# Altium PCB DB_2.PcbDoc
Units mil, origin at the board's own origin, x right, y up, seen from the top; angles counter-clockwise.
Board outline 1675 x 1950 mil, 4 copper layers (Top Layer, Signal Layer 1, Ground, Bottom Layer), stack 30.634 mil thick; 76 components, 70 nets, 293 pads, 58 vias.
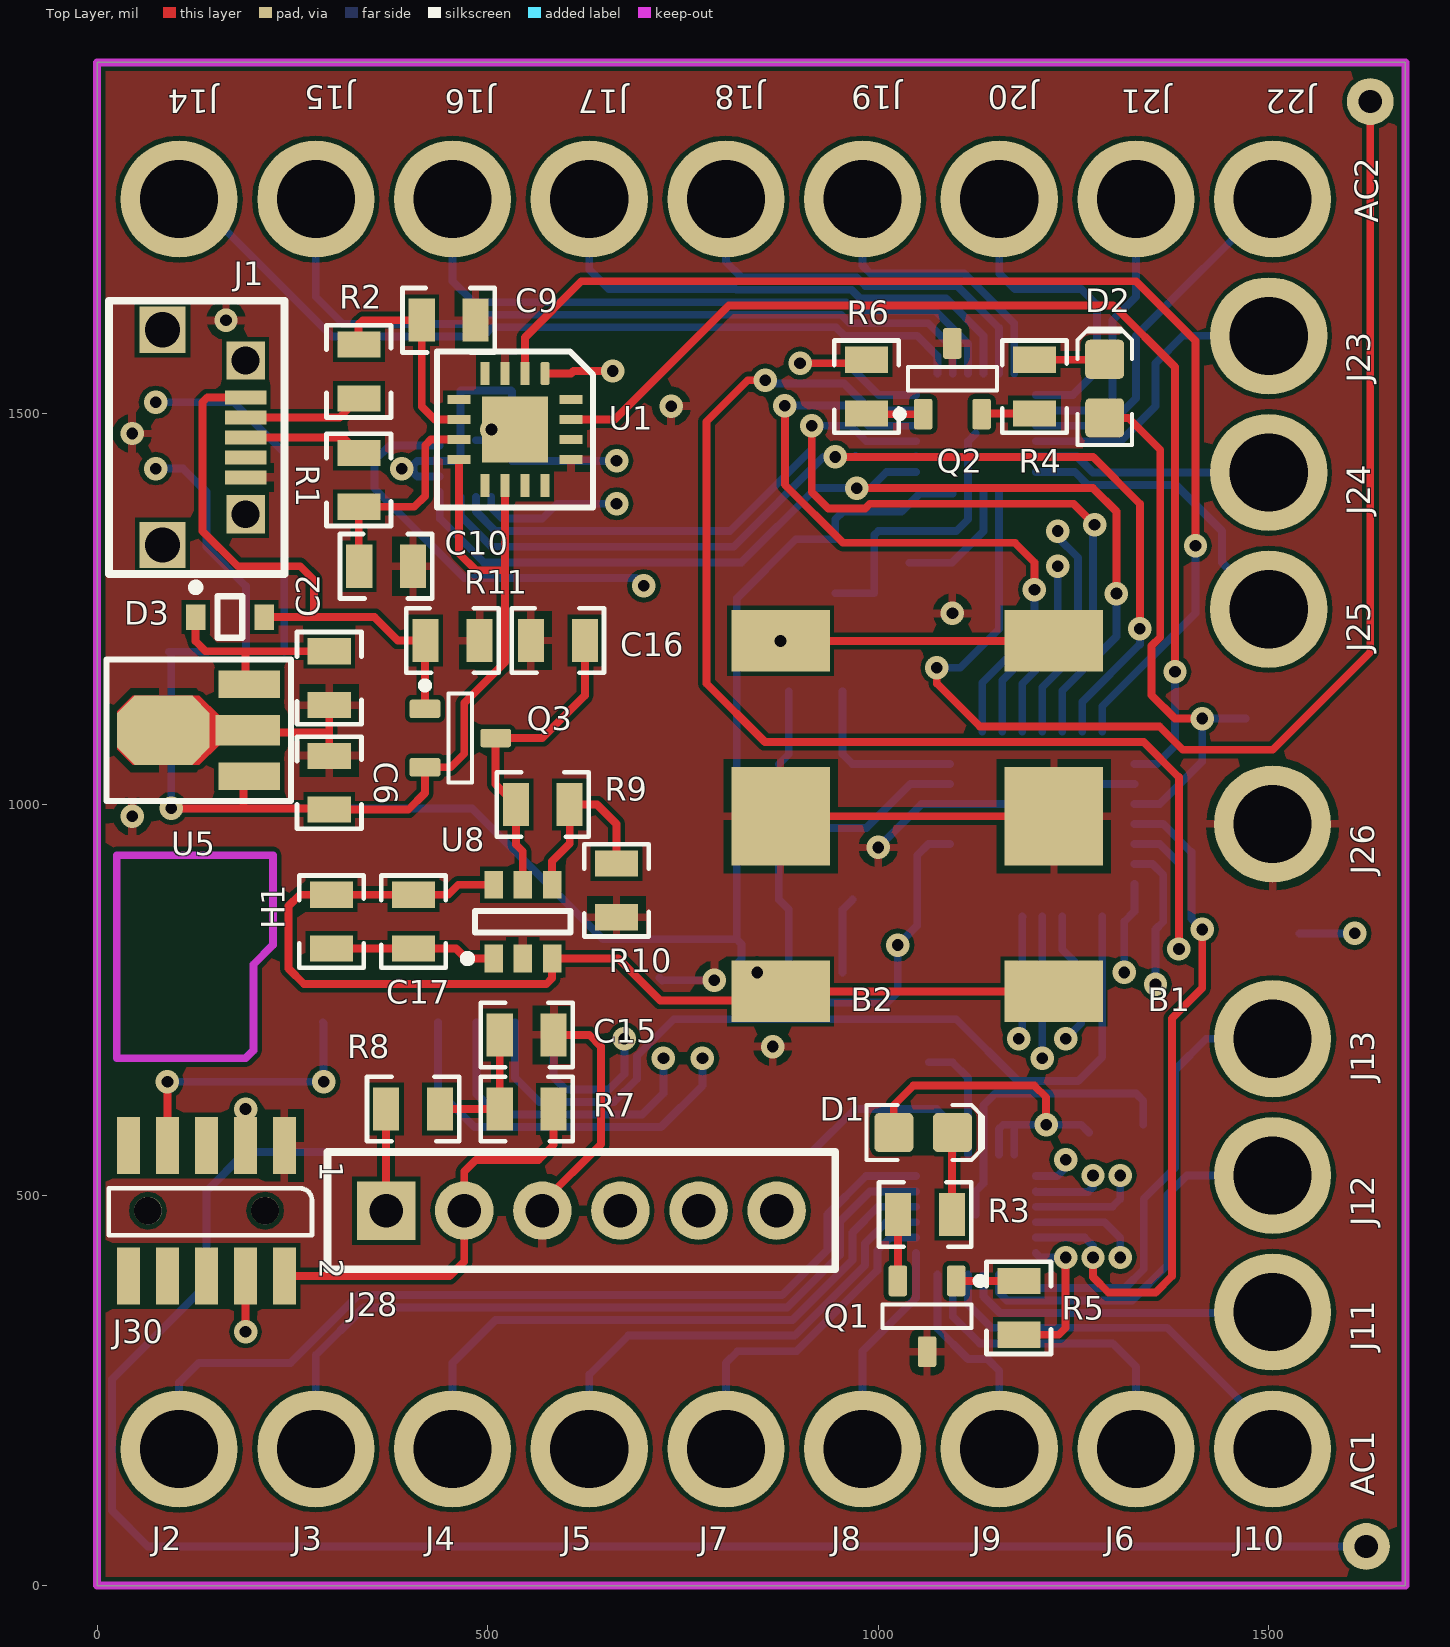
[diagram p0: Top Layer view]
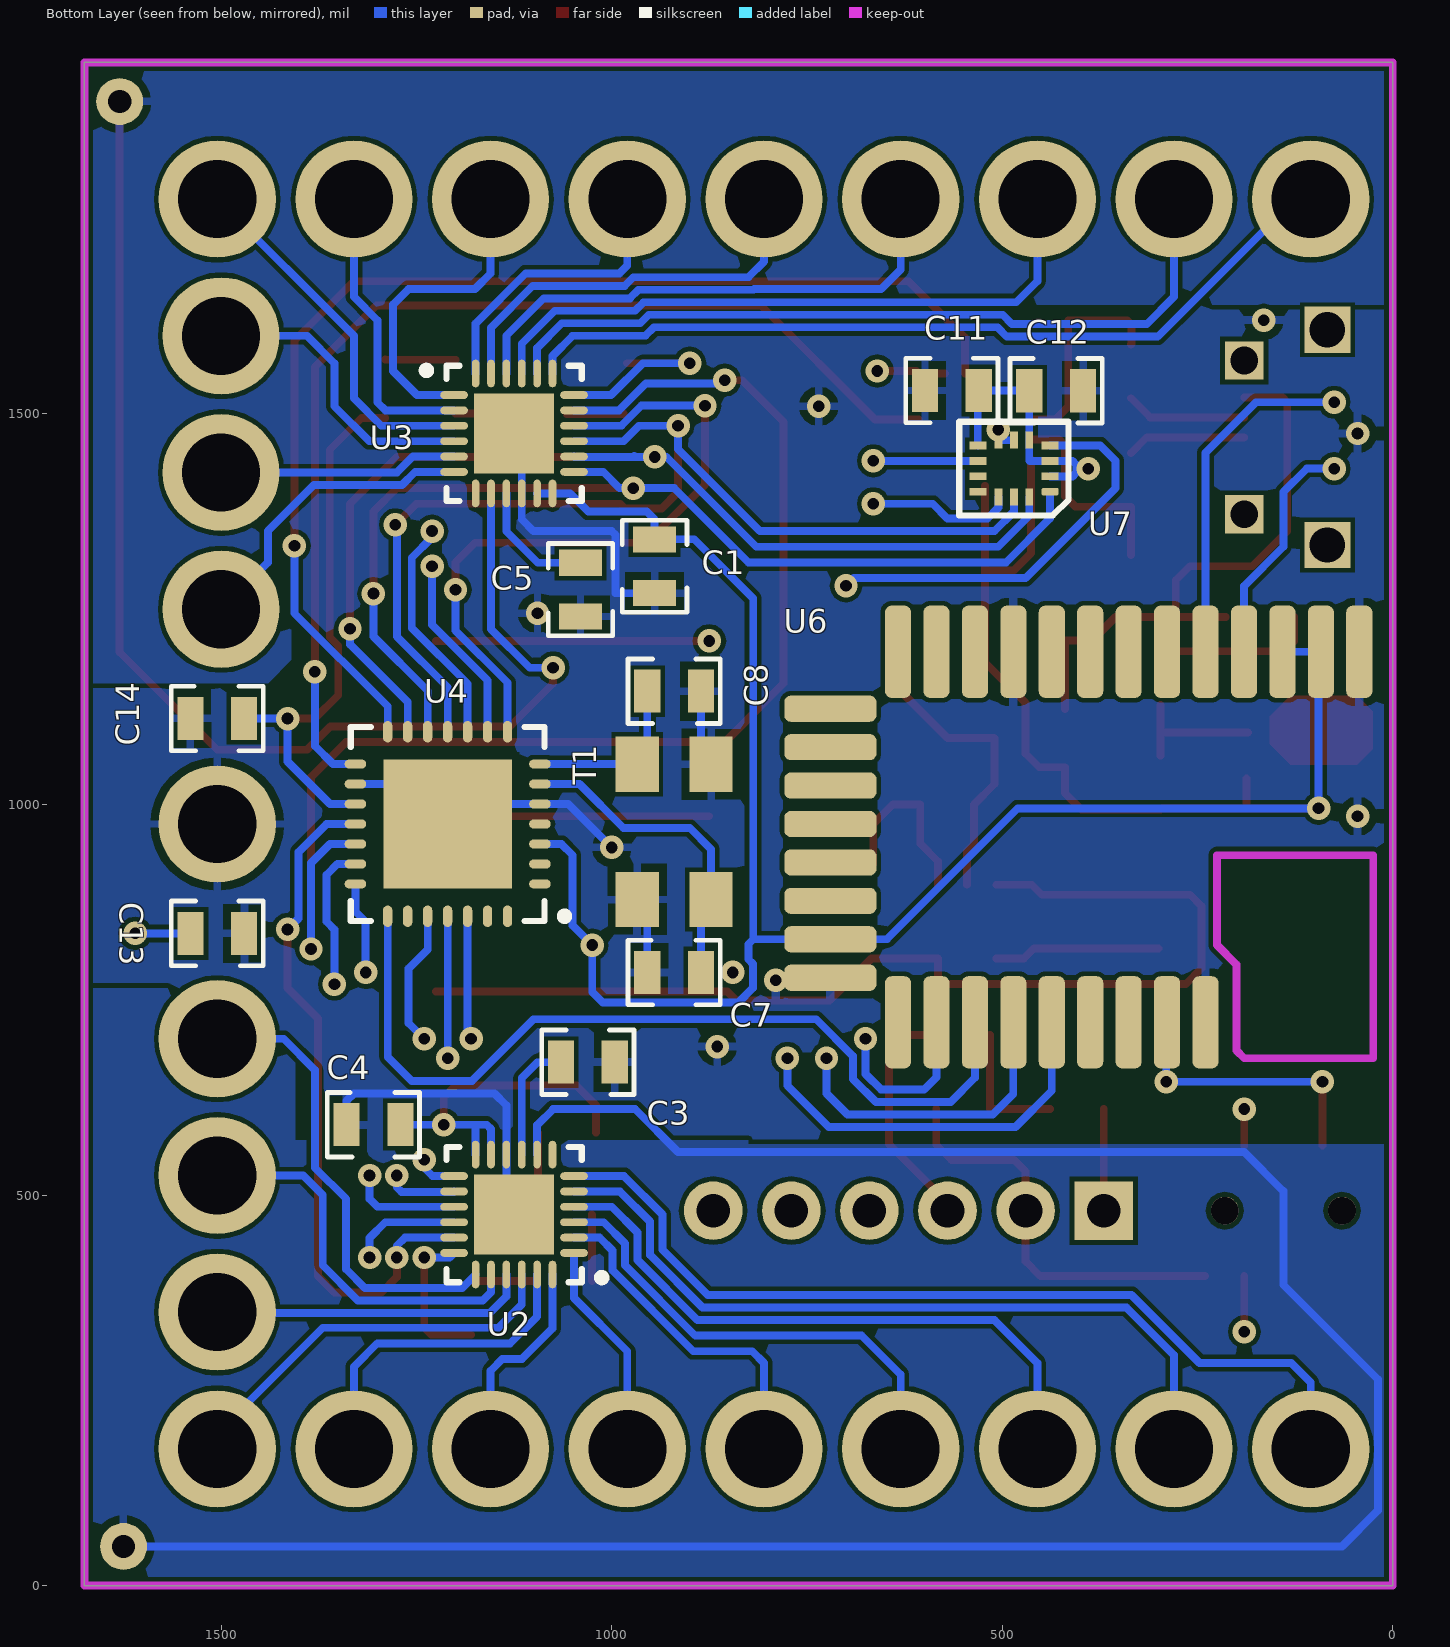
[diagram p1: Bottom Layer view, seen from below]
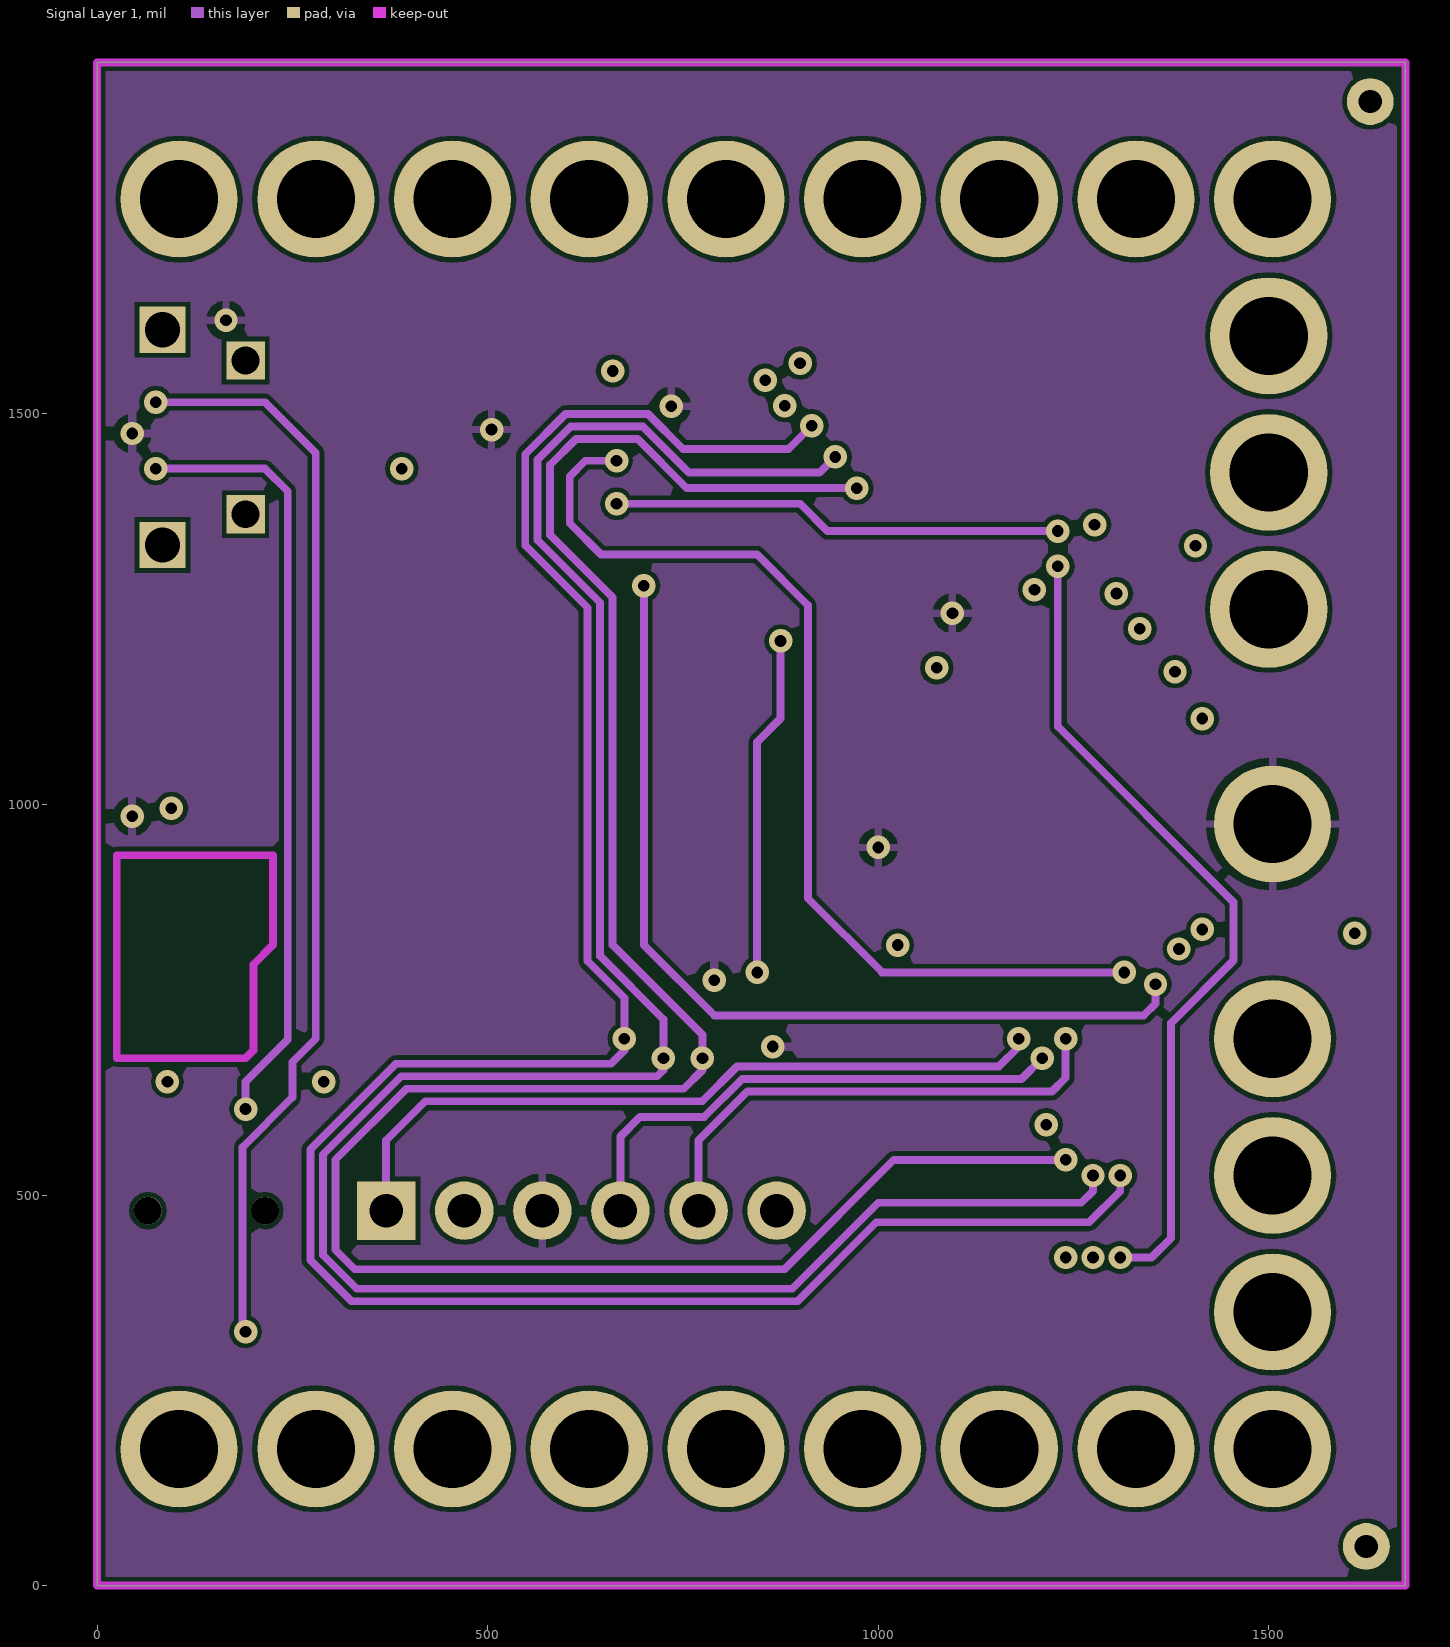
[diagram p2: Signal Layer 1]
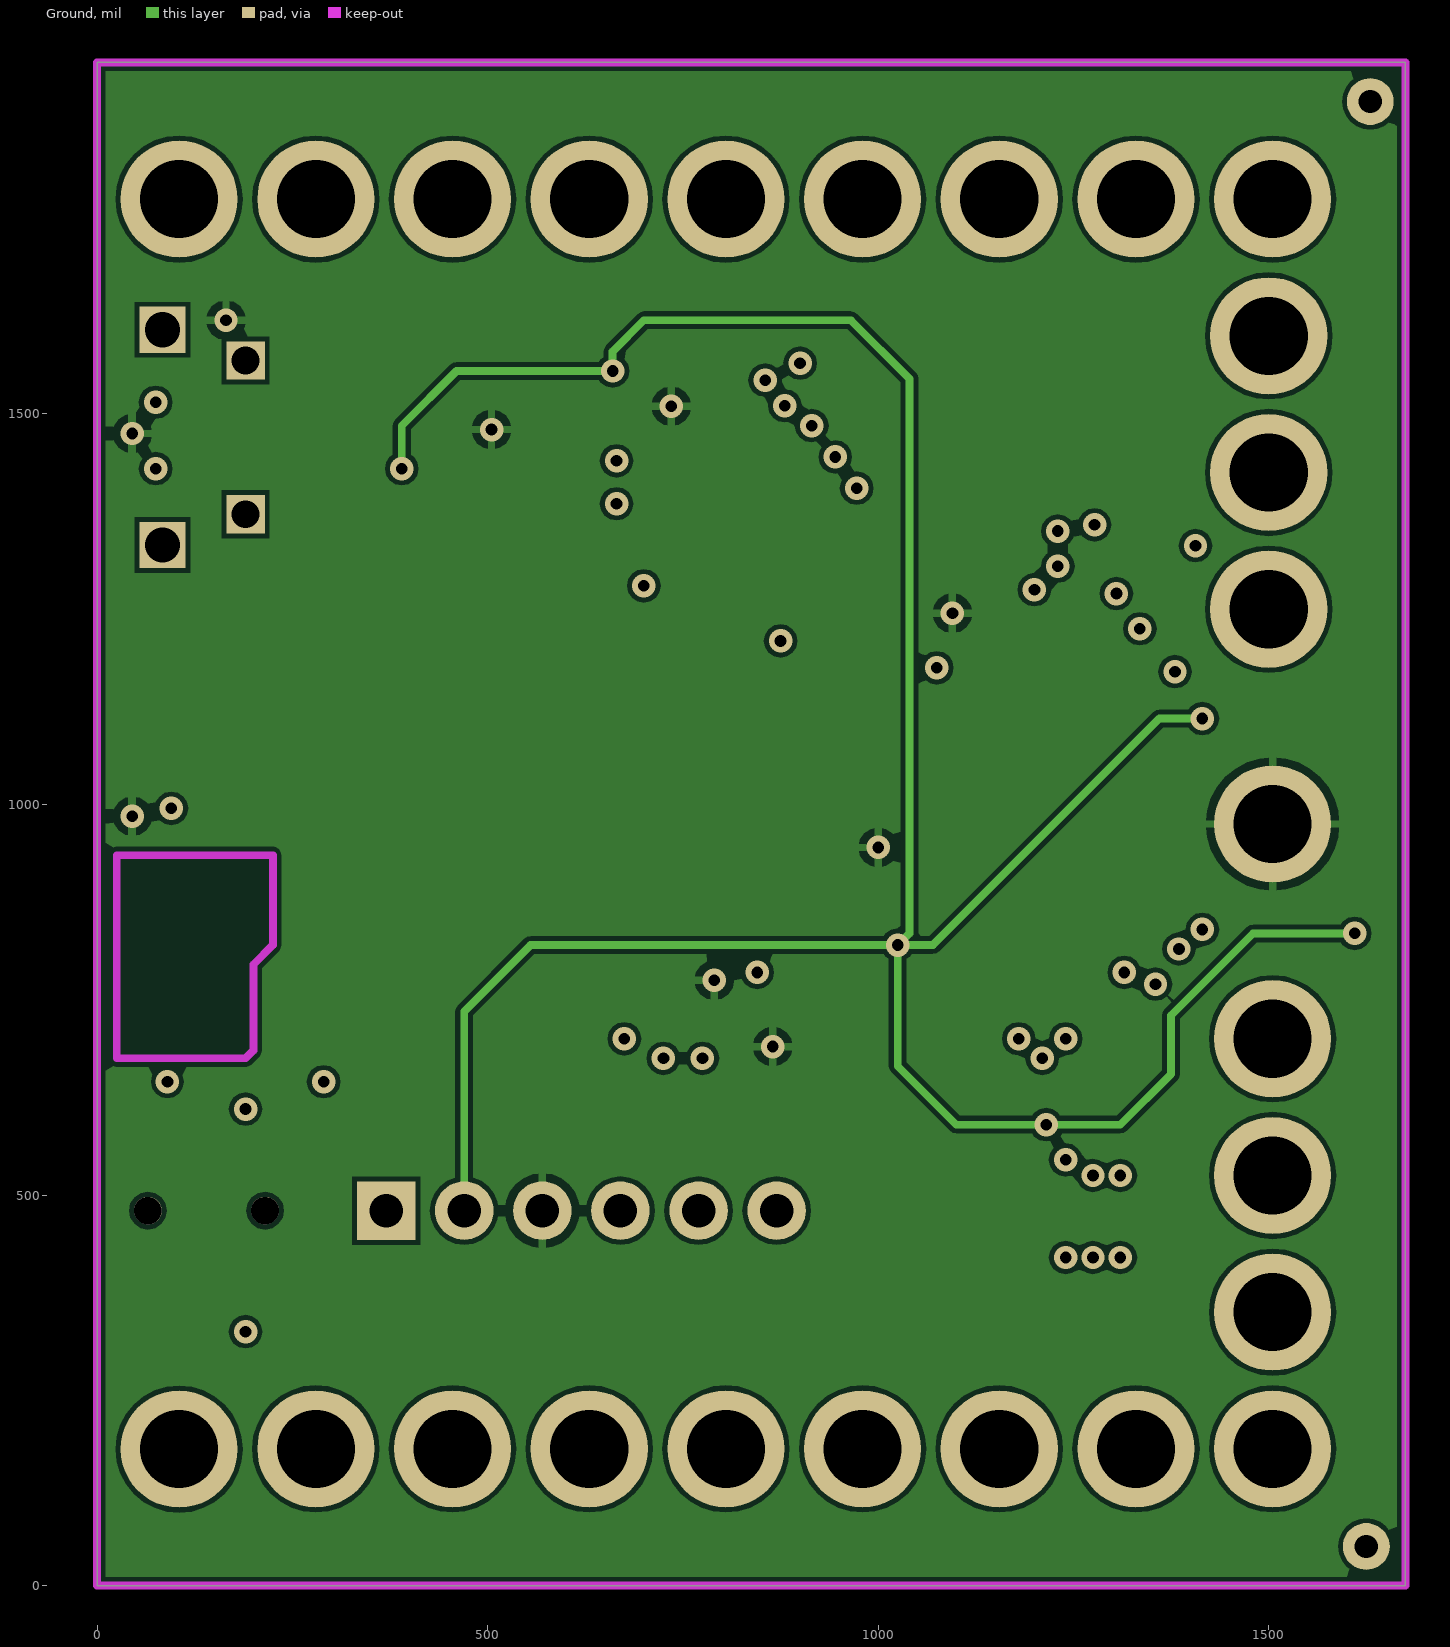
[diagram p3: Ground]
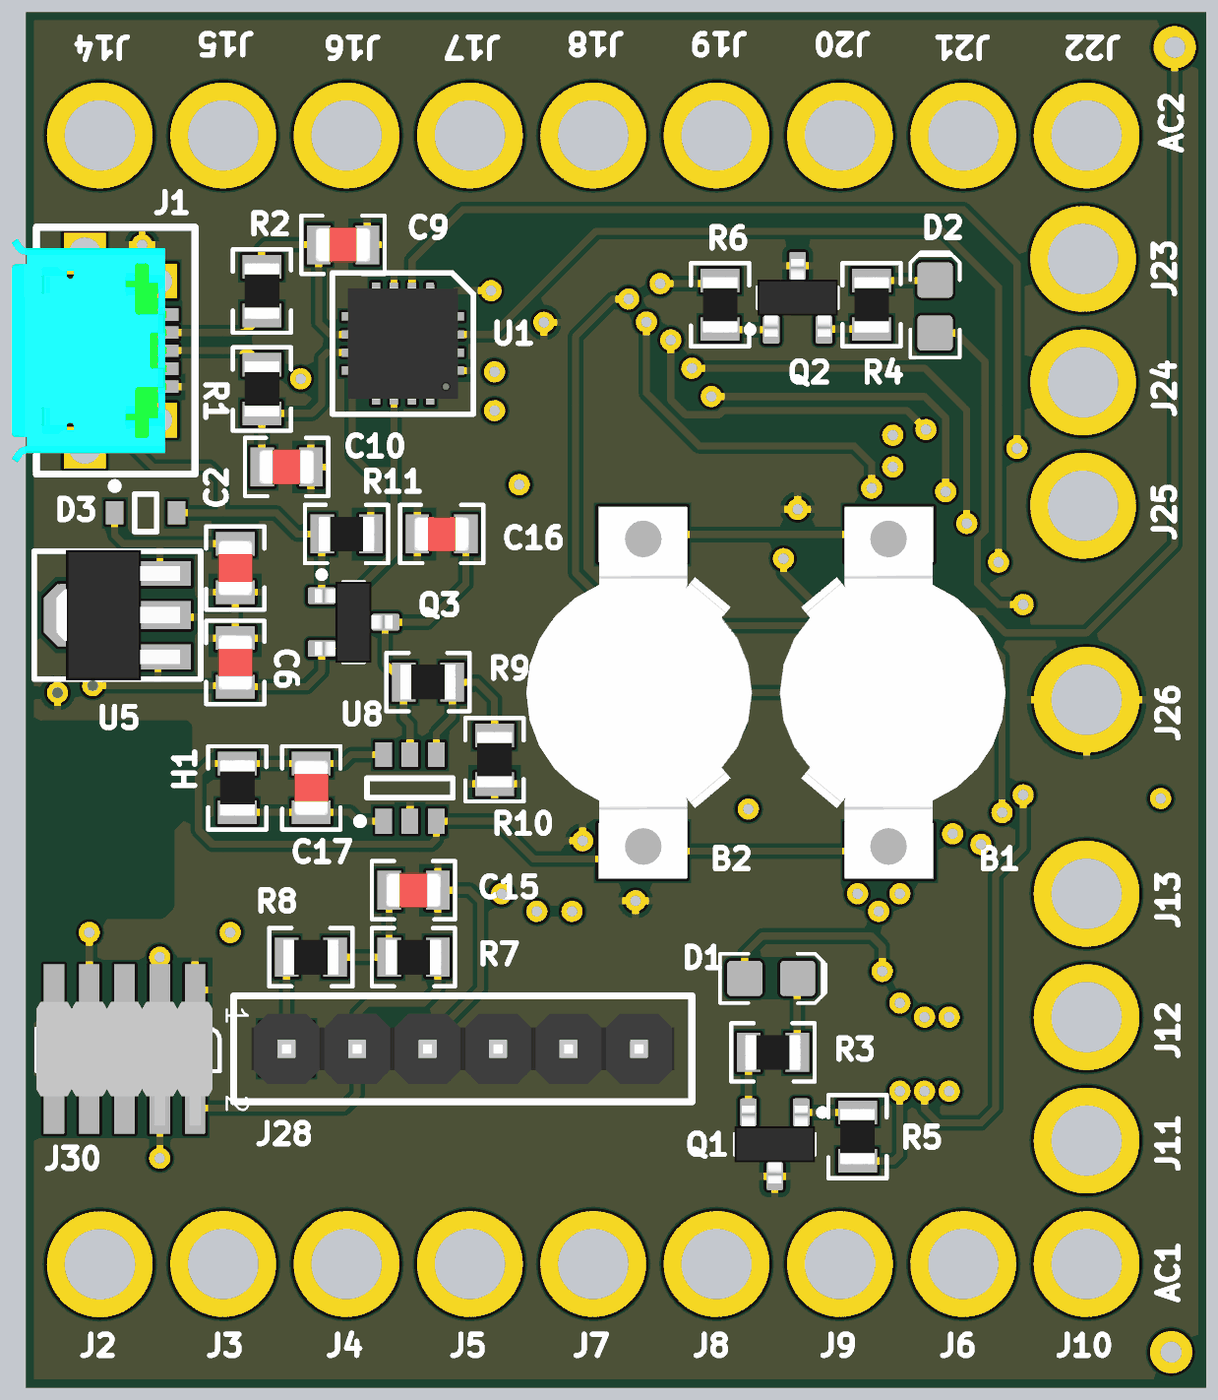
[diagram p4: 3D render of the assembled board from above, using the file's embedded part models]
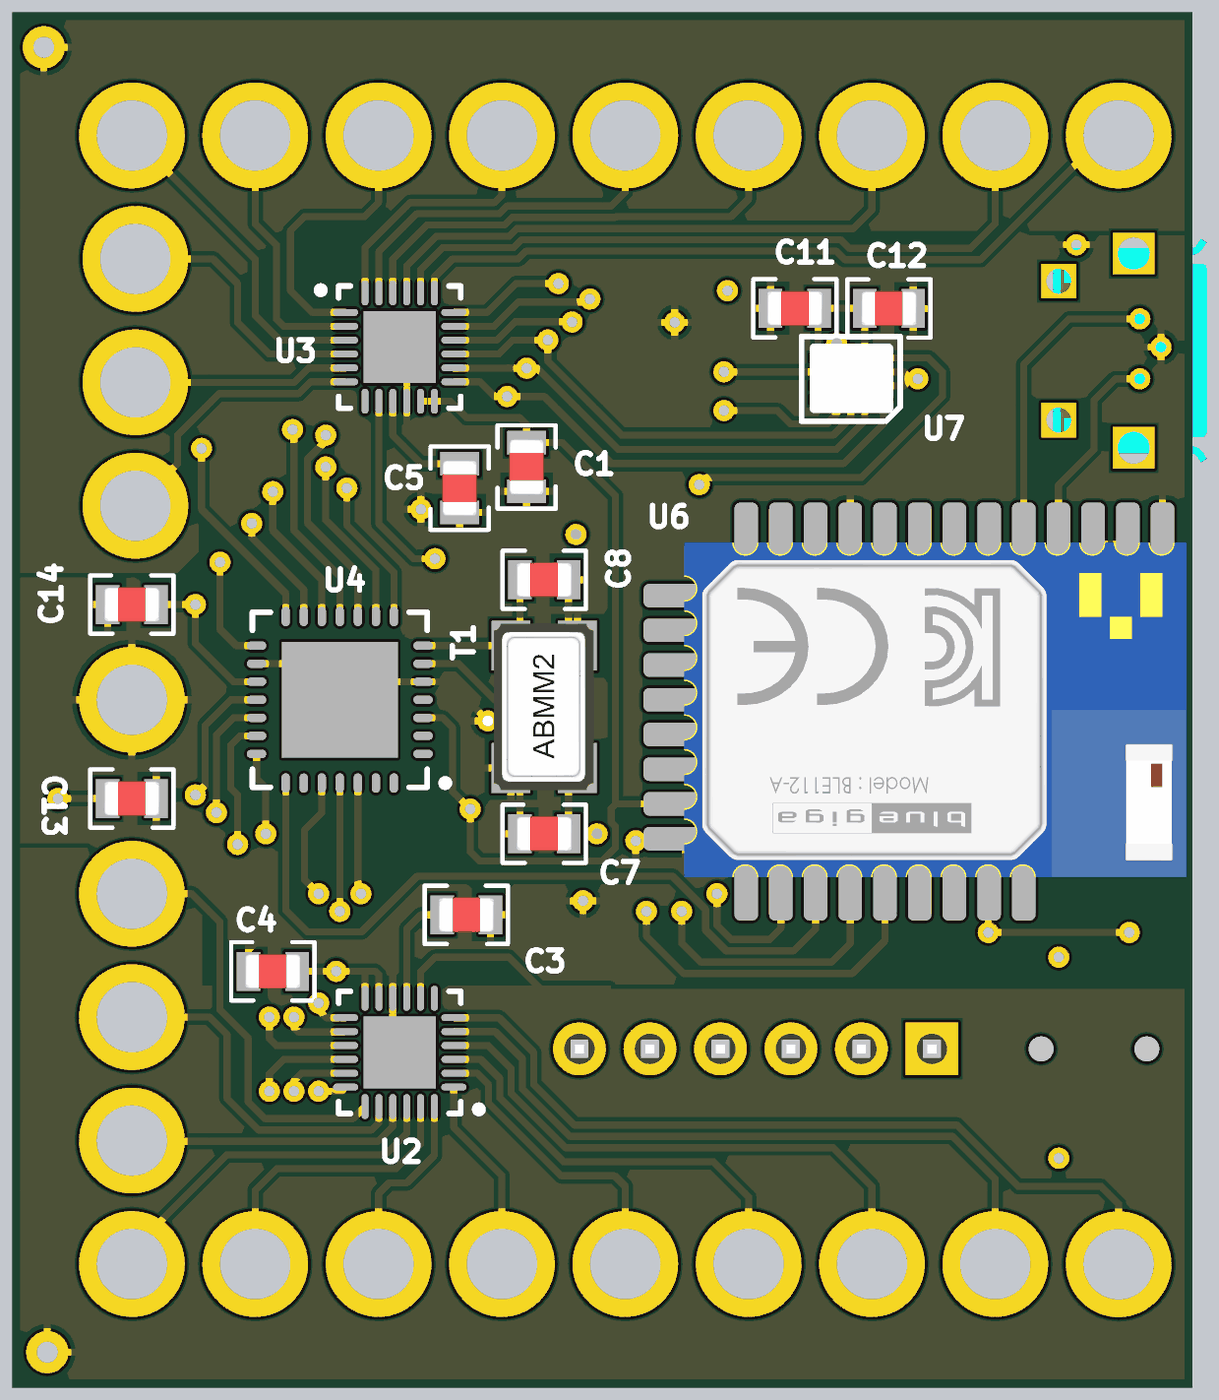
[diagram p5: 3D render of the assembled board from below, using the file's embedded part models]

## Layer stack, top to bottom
Top Solder: solder mask 0.4, Solder Resist, Dk 3.5
Top Layer: signal copper 1.4
Dielectric 1: core 10, FR-4, Dk 4.2
Signal Layer 1: signal copper 1.417
Dielectric 3: prepreg 5, Dk 4.2
Ground: signal copper 1.417
Dielectric 2: core 10, Dk 4.2
Bottom Layer: signal copper 1.4
Bottom Solder: solder mask 0.4, Solder Resist, Dk 3.5

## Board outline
0,0 1675,0 1675,1950 0,1950

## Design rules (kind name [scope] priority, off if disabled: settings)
Clearance [All] p1: gap=6 ignorepadtopadclearanceinfootprint=FALSE except(0: Arc-Hole Track-Hole SMDPad-Hole THPad-Hole Via-Hole Fill-Hole Poly-Hole Region-Hole Text-Hole)
HoleSize [All] p1: absolutevalues=TRUE maxlimit=200 minlimit=1 maxpercent=80.000 minpercent=20.000
HoleToHoleClearance [All] p1: gap=6 allowstackedmicrovias=TRUE
MinimumSolderMaskSliver [All] p1: minsoldermaskwidth=6
PolygonConnect [All] p1: connectstyle=Relief reliefconductorwidth=10 reliefentries=4 polygonreliefangle="90 Angle" airgapwidth=10
RoutingVias [All] p1: holewidth=28 width=50 viastyle="Through Hole" minholewidth=3 minwidth=8 maxholewidth=28 maxwidth=50
SilkToSilkClearance [All] p1: silktosilkclearance=6
SilkToSolderMaskClearance [IsPad] p1: minsilkscreentomaskgap=6 clearancetoexposedcopper=TRUE
SolderMaskExpansion [All] p1: expansion=4
Width [All] p1: maxlimit=50 minlimit=6 preferedwidth=10
25 further rules are at their usual default settings.

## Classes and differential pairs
component class Battery: B1 B2 C2 C6 C9 C10 C16 C17 D3 H1 J1 Q3 R1 R2 R9 R10 R11 U5 U8
component class Sheet-2: AC1 AC2 C1 C3 C4 C5 C7 C8 C11 C12 C13 C14 C15 D1 D2 J2 J3 J4 J5 J6 J7 J8 J9 J10 J11 J12 J13 J14 J15 J16 J17 J18 J19 J20 J21 J22 J23 J24 J25 J26 J28 J30 Q1 Q2 R3 R4 R5 R6 R7 R8 T1 U1 U2 U3 U4 U6 U7

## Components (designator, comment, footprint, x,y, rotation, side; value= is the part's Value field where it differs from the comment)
AC1 "AC_Shield" AC_SHIELD 1625,50 r0 top
AC2 "AC_Shield" AC_SHIELD 1630,1900 r90 top
B1 "XR48" XR48 1225,985 r270 top
B2 "XR48" XR48 875,985 r90 top
C1 "0.1µF" CAP-0805(2012)-R 945,1305 r270 bottom
C2 "0.33µF" CAP-0805(2012)-R 297.17,1161.73 r270 top
C3 "10000pF" CAP-0805(2012)-R 1030.55,670 r180 bottom
C4 "0.1µF" CAP-0805(2012)-R 1305,590 r0 bottom
C5 "10000pF" CAP-0805(2012)-R 1040,1275 r270 bottom
C6 "0.1µF" CAP-0805(2012)-R 297.17,1027.83 r90 top
C7 "18pF" CAP-0805(2012)-R 920,785 r0 bottom
C8 "18pF" CAP-0805(2012)-R 920,1145 r180 bottom
C9 "47pF" CAP-0805(2012)-R 450,1620 r180 top
C10 "47pF" CAP-0805(2012)-R 370,1305 r180 top
C11 "0.1µF" CAP-0805(2012)-R 564.45,1530 r180 bottom
C12 "10000pF" CAP-0805(2012)-R 430.87,1529.68 r0 bottom
C13 "0.1µF" CAP-0805(2012)-R 1505,835 r180 bottom
C14 "0.1µF" CAP-0805(2012)-R 1505,1110 r0 bottom
C15 "0.1uF" CAP-0805(2012)-R 550,705 r0 top
C16 "10uF" CAP-0805(2012)-R 590,1210 r180 top
C17 "4.7uF" CAP-0805(2012)-R 405,850 r270 top
D1 "YELLOW" LED-0805-A 1057.5,580 r0 top
D2 "YELLOW" LED-0805-A 1290,1532.5 r90 top
D3 "Shottky_Diode" SOD-323-2 170,1240 r0 top
H1 "H-0805(2012)" H-0805(2012)-H 300,850 r90 top
J1 "USB" USB_CONNECTOR_5P_MICRO_USB_FCI 190,1470 r270 top
J2 "Conductive Thread" THREAD_HOLE 105,174.61 r180 top
J3 "Conductive Thread" THREAD_HOLE 280,175 r180 top
J4 "Conductive Thread" THREAD_HOLE 455,175 r180 top
J5 "Conductive Thread" THREAD_HOLE 630,175 r180 top
J6 "Conductive Thread" THREAD_HOLE 1330,175 r180 top
J7 "Conductive Thread" THREAD_HOLE 805,175 r180 top
J8 "Conductive Thread" THREAD_HOLE 980,175 r180 top
J9 "Conductive Thread" THREAD_HOLE 1155,175 r180 top
J10 "Conductive Thread" THREAD_HOLE 1505,175 r180 top
J11 "Conductive Thread" THREAD_HOLE 1505,350 r180 top
J12 "Conductive Thread" THREAD_HOLE 1505,525 r180 top
J13 "Conductive Thread" THREAD_HOLE 1505,700 r270 top
J14 "Conductive Thread" THREAD_HOLE 105,1775 r0 top
J15 "Conductive Thread" THREAD_HOLE 280,1775 r180 top
J16 "Conductive Thread" THREAD_HOLE 455,1775 r0 top
J17 "Conductive Thread" THREAD_HOLE 630,1775 r180 top
J18 "Conductive Thread" THREAD_HOLE 805,1775 r180 top
J19 "Conductive Thread" THREAD_HOLE 980,1775 r180 top
J20 "Conductive Thread" THREAD_HOLE 1155,1775 r180 top
J21 "Conductive Thread" THREAD_HOLE 1330,1775 r180 top
J22 "Conductive Thread" THREAD_HOLE 1505,1775 r180 top
J23 "Conductive Thread" THREAD_HOLE 1500,1600 r90 top
J24 "Conductive Thread" THREAD_HOLE 1500,1425 r90 top
J25 "Conductive Thread" THREAD_HOLE 1500,1250 r90 top
J26 "Conductive Thread" THREAD_HOLE 1505,975 r180 top
J28 "Header 6 pin" HEADER-6-100MIL 370,480 r0 top
J30 "GRPB052VWQP-RC" GRPB052VWQP-RC 40,563.5 r270 top
Q1 "Value" SOT23-3 1062.6,344.72 r90 top
Q2 "Value" SOT23-3 1095,1545 r270 top
Q3 "DMP1045U" SOT23-3 465,1085 r180 top
R1 "27" R-0805(2012)-R 335,1415.55 r270 top
R2 "27" R-0805(2012)-R 335,1554.45 r90 top
R3 "30" R-0805(2012)-R 1060,475 r0 top
R4 "30" R-0805(2012)-R 1200,1535 r90 top
R5 "1k" R-0805(2012)-R 1180,355.55 r270 top
R6 "1k" R-0805(2012)-R 985,1535 r270 top
R7 "10k" R-0805(2012)-R 550,610 r0 top
R8 "330" R-0805(2012)-R 404.45,610 r0 top
R9 "976KR" R-0805(2012)-R 570.55,1000 r0 top
R10 "562KR" R-0805(2012)-R 665,890 r270 top
R11 "10KR" R-0805(2012)-R 455,1210 r180 top
T1 "8MHz" CRYSTAL-8MHZ 920,965 r90 bottom
U1 "FT230XQ-R" QFN-16 535,1480 r270 top
U2 "ADI-AD7147" LFCSP_WQ 1125,475 r0 bottom
U3 "ADI-AD7147" LFCSP_WQ 1125,1475 r180 bottom
U4 "PIC18F25K80" MCHP-QFN-S-MM28_N 1210,975 r0 bottom
U5 "L78L33ACUTR" SOT89-3 130,1095 r180 top
U6 "BLE112-A-V1" BLE112-A-V1 720,1195.47 r270 bottom
U7 "LSM6DS3H" LGA-14 485,1430 r0 bottom
U8 "MCP1640BT-I/CHY" MCHP-SOT-23-CHY6_L 545,850 r90 top

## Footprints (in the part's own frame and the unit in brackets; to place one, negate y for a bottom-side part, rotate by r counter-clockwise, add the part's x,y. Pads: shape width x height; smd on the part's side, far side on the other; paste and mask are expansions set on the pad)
AC_SHIELD [mil]
  round 60 hole 30: 1(0,0)
BLE112-A-V1 [mm] "CLASS 2 BLTOOTH 4.0 MODULE"
  rrect50% 3x0.85 smd: 1(0,17.2) 2(0,15.95) 3(0,14.7) 4(0,13.45) 5(0,12.2) 6(0,10.95) 7(0,9.7) 8(0,8.45) 9(0,7.2) 10(0,5.95) 11(0,4.7) 12(0,3.45) 13(0,2.2) 22(12.05,2.2) 23(12.05,3.45) 24(12.05,4.7) 25(12.05,5.95) 26(12.05,7.2) 27(12.05,8.45) 28(12.05,9.7) 29(12.05,10.95) 30(12.05,12.2)
  rrect50% 0.85x3 smd: 14(1.85,0) 15(3.1,0) 16(4.35,0) 17(5.6,0) 18(6.85,0) 19(8.1,0) 20(9.35,0) 21(10.6,0)
  body extent -0.06,-0.03 11.99,18.07, height 2.3
CAP-0805(2012)-R [mm] "Capacitor 0805(2012) Reflow"
  rect 0.85x1.4 smd: 1(-0.875,0) 2(0.875,0)
  silkscreen extent -1.5,-1.05 1.5,1.05, body extent -1,-0.63 1,0.63, height 0.78
CRYSTAL-8MHZ [mm] "ABRACON ABMM2-8.000MHZ-E2-T"
  rect 1.8x1.4 smd: 1(-2.2,-1.2) 2(-2.2,1.2) 2(2.2,-1.2) 3(2.2,1.2)
  body extent -3,-1.78 3,1.82, height 1.21
GRPB052VWQP-RC [mm] "CONN HEADER .050\" 10PS DL SMD AU"
  rect 1.85x0.74 smd: 1(0,5.08) 2(4.25,5.08) 3(0,3.81) 4(4.25,3.81) 5(0,2.54) 6(4.25,2.54) 7(0,1.27) 8(4.25,1.27) 9(0,0) 10(4.25,0)
  round 0.9 hole 0.9 unplated: 21(2.121,0.635) 22(2.121,4.445)
  silkscreen extent 1.4,-0.63 2.92,5.97, body extent -0.62,-0.63 4.88,5.72, height 4.1
H-0805(2012)-H [mm] "Inductor 0805(2012) Reflow"
  rect 0.85x1.4 smd: 1(-0.875,0) 2(0.875,0)
  silkscreen extent -1.5,-1.05 1.5,1.05, body extent -1,-0.62 1,0.63, height 0.5
HEADER-6-100MIL [mil] "100 mil spacing"
  rect 75x75 hole 43: 1(0,0)
  round 75 hole 43: 2(100,0) 3(200,0) 4(300,0) 5(400,0) 6(500,0)
  silkscreen extent -75,-75 575,75, body extent -50,-50 550,50, height 339
LED-0805-A [mil]
  round 20 on Mech14: 0(0,0)
  rrect25% 50x50 smd: A(-37.5,0) K(37.5,0)
  Top Layer pour cut-out: -15,30 15,30 15,-30 -15,-30
  silkscreen extent -72,-35 77,35, body extent -39,-25 39,25, height 31
LFCSP_WQ [mm] "QFN, 24-Leads, Body 4x4mm, Pitch 0.5mm, Thermal Pad 2.5x2.5mm, IPC Medium Density"
  oval 0.9x0.25 smd: 1(-1.95,1.25) 2(-1.95,0.75) 3(-1.95,0.25) 4(-1.95,-0.25) 5(-1.95,-0.75) 6(-1.95,-1.25) 13(1.95,-1.25) 14(1.95,-0.75) 15(1.95,-0.25) 16(1.95,0.25) 17(1.95,0.75) 18(1.95,1.25)
  oval 0.25x0.9 smd: 7(-1.25,-1.95) 8(-0.75,-1.95) 9(-0.25,-1.95) 10(0.25,-1.95) 11(0.75,-1.95) 12(1.25,-1.95) 19(1.25,1.95) 20(0.75,1.95) 21(0.25,1.95) 22(-0.25,1.95) 23(-0.75,1.95) 24(-1.25,1.95)
  rect 2.6x2.6 smd: 25(0,0)
  silkscreen extent -2.97,-2.2 2.2,2.2, body extent -2.05,-2.05 2.05,2.05, height 1
LGA-14 [mm] "LGA-14 2.5X3X0.86 14L"
  rrect50% 0.55x0.25 smd: 1(-1.175,0.75)
  rect 0.55x0.25 smd: 2(-1.175,0.25) 3(-1.175,-0.25) 4(-1.175,-0.75) 8(1.175,-0.75) 9(1.175,-0.25) 10(1.175,0.25) 11(1.175,0.75)
  rect 0.25x0.55 smd: 5(-0.5,-0.925) 6(0,-0.925) 7(0.5,-0.925) 12(0.5,0.925) 13(0,0.925) 14(-0.5,0.925)
  silkscreen extent -1.78,-1.52 1.78,1.52, body extent -1.52,-1.27 1.48,1.23, height 0.86
MCHP-QFN-S-MM28_N [mm] "QFN, 28-Leads, Body 6x6mm, Pitch 0.65mm, Thermal Pad 4.175x4.175mm, IPC Medium Density"
  oval 0.7x0.3 smd: 1(-3,1.95) 2(-3,1.3) 3(-3,0.65) 4(-3,0) 5(-3,-0.65) 6(-3,-1.3) 7(-3,-1.95) 15(3,-1.95) 16(3,-1.3) 17(3,-0.65) 18(3,0) 19(3,0.65) 20(3,1.3) 21(3,1.95)
  oval 0.3x0.7 smd: 8(-1.95,-3) 9(-1.3,-3) 10(-0.65,-3) 11(0,-3) 12(0.65,-3) 13(1.3,-3) 14(1.95,-3) 22(1.95,3) 23(1.3,3) 24(0.65,3) 25(0,3) 26(-0.65,3) 27(-1.3,3) 28(-1.95,3)
  rect 4.18x4.18 smd: 29(0,0)
  silkscreen extent -3.92,-3.15 3.15,3.15, body extent -3,-3 3,3, height 1
MCHP-SOT-23-CHY6_L [mm] "SOT23, 6-Leads, Body 2.9x1.55mm, Pitch 0.95mm, IPC High Density"
  rect 0.9x0.6 smd: 1(-1.2,0.95) 2(-1.2,0) 3(-1.2,-0.95) 4(1.2,-0.95) 5(1.2,0) 6(1.2,0.95)
  silkscreen extent -1.32,-1.55 0.35,1.92, body extent -0.9,-1.55 0.9,1.55, height 1.45
QFN-16 [mm]
  rrect50% 0.75x0.3 smd: 1(-1.825,0.975)
  rect 0.75x0.3 smd: 2(-1.825,0.325) 3(-1.825,-0.325) 4(-1.825,-0.975) 9(1.825,-0.975) 10(1.825,-0.325) 11(1.825,0.325) 12(1.825,0.975)
  rect 0.3x0.75 smd: 5(-0.975,-1.825) 6(-0.325,-1.825) 7(0.325,-1.825) 8(0.975,-1.825) 13(0.975,1.825) 14(0.325,1.825) 15(-0.325,1.825) 16(-0.975,1.825)
  rect 2.15x2.15 smd: 17(0,0)
  silkscreen extent -2.54,-2.54 2.54,2.54, body extent -2,-2 2,2, height 0.92
R-0805(2012)-R [mm] "Resistor 0805(2012) Reflow"
  rect 0.85x1.4 smd: 1(-0.875,0) 2(0.875,0)
  silkscreen extent -1.5,-1.05 1.5,1.05, body extent -1,-0.62 1,0.63, height 0.5
SOD-323-2 [mm] "SOD, 2-Leads, Body 1.7x1.25mm"
  rect 0.63x0.83 smd: 1(-1.115,0) 2(1.115,0)
  silkscreen extent -1.24,-0.67 0.4,1.09, body extent -0.85,-0.63 0.85,0.63, height 1.06
SOT23-3 [mm] "SOT23, 3 pin"
  round 0.5 on Mech14: 0(0,0)
  rrect25% 1x0.6 smd: 1(1.15,-0.95) 2(-1.15,0) 3(1.15,0.95)
  silkscreen extent -0.38,-1.81 1.25,1.45, body extent -1.4,-1.45 1.4,1.45, height 1.29
SOT89-3 [mm] "JEDEC TO-243 option AA / SOT89"
  round 1 on Mech14: 0(0,0)
  rrect1% 2x0.9 smd: 1(-1.65,1.5) 3(-1.65,-1.5)
  rrect1% 2.1x1 smd: 2(-1.6,0)
  oct 3x2.25 smd: 2(1.15,0)
  Top Layer region: -0.7,-0.45 -0.025,-1.125 2.15,-1.125 2.65,-0.625 2.65,0.625 2.15,1.125 -0.025,1.125 -0.7,0.45
  silkscreen extent -3,-2.3 3,2.3, body extent -2.25,-2.35 2.2,2.35, height 1.69
THREAD_HOLE [mil] "MAGNETIC_THREAD_HOLE"
  round 150 hole 100: 1(0,0)
USB_CONNECTOR_5P_MICRO_USB_FCI [mm] "USB_Connector_5P_MICRO_USB_FCI_TypeB"
  rect 0.45x1.35 smd: 1(-1.3,0) 2(-0.65,0) 3(0,0) 4(0.65,0) 5(1.3,0)
  rect 1.25x1.25 hole 0.9: 15(2.5,0) 16(-2.5,0)
  rect 1.5x1.5 hole 1.15: 18(-3.5,-2.7) 18(3.5,-2.7)
  silkscreen extent -4.44,-4.45 4.45,1.27, body extent -4.02,-5.33 4.02,0.25, height 2.73
XR48 [mm] "Size 13 Coin Cell Battery"
  rect 3.2x3.2 smd: 1(0,0)
  rect 2x3.2 smd: 2(-5.7,0) 2(5.7,0)
  body extent -6.68,-3.95 6.68,4.19, height 5.75

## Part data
C1 C4 C6 C11 C13 C14: library part C-0805(2012), "___ OHM ___ mW 0805(2012) SMD", Manufacturer=Yageo, Manufacturer Part Number=CC0805KRX7R9BB104, Operating Temperature="-55°C ~ 125°C", Package / Case="0805 (2012 Metric)", Ratings=-, Supplier Part Number 1=311-1140-1-ND, Temperature Coefficient=X7R, Tolerance=±10%, Voltage - Rated=50V
C2: library part C-0805(2012), "___ OHM ___ mW 0805(2012) SMD", Manufacturer=Yageo, Manufacturer Part Number=CC0805KKX7R7BB334, Operating Temperature="-55°C ~ 125°C", Package / Case="0805 (2012 Metric)", Ratings=-, Supplier Part Number 1=311-1882-1-ND, Temperature Coefficient=X7R, Tolerance=±10%, Voltage - Rated=16V
C3 C5 C12: library part C-0805(2012), "___ OHM ___ mW 0805(2012) SMD", Manufacturer=Yageo, Manufacturer Part Number=CC0805KRX7R9BB103, Operating Temperature="-55°C ~ 125°C", Package / Case="0805 (2012 Metric)", Ratings=-, Supplier Part Number 1=311-1136-1-ND, Temperature Coefficient=X7R, Tolerance=±10%, Voltage - Rated=50V
C7 C8: library part C-0805(2012), "___ OHM ___ mW 0805(2012) SMD", Manufacturer=Yageo, Manufacturer Part Number=CC0805JRNPO9BN180, Operating Temperature="-55°C ~ 125°C", Package / Case="0805 (2012 Metric)", Ratings=-, Supplier Part Number 1=311-1102-1-ND, Temperature Coefficient="C0G, NP0", Tolerance=±5%, Voltage - Rated=50V
C9 C10: library part C-0805(2012), "___ OHM ___ mW 0805(2012) SMD", Manufacturer=Yageo, Manufacturer Part Number=CC0805JRNPO9BN470, Operating Temperature="-55°C ~ 125°C", Package / Case="0805 (2012 Metric)", Ratings=-, Supplier Part Number 1=311-1107-1-ND, Temperature Coefficient="C0G, NP0", Tolerance=±5%, Voltage - Rated=50V
C15: library part C-0805(2012), "___ OHM ___ mW 0805(2012) SMD"
C16: library part C-0805(2012), "___ OHM ___ mW 0805(2012) SMD", Case/Package=0805, Case Code (Metric)=2012, Dielectric=X5R, Manufacturer=Murata, Manufacturer Part Number=GRM219R61A106KE44D, Max Operating Temperature=85°C, Min Operating Temperature=-55°C, Package Quantity=1, Supplier Part Number 1=81-GRM219R61A106KE4D, Tolerance=10%, Voltage=10V
C17: library part C-0805(2012), "___ OHM ___ mW 0805(2012) SMD", Case/Package=0805, Case Code (Metric)=2012, Dielectric=X5R, Manufacturer=Murata, Manufacturer Part Number=GRM21BR61C475KA88L, Max Operating Temperature=85°C, Min Operating Temperature=-55°C, Package Quantity=1, Supplier Part Number 1=81-GRM21BR61C475KA8L, Tolerance=10%, Voltage=16V
D1 D2: library part LED_0805_YELLOW, "LED, 0805 SMD, YELLOW", Color=Yellow, Current - Test=20mA, Lens Color=White, Manufacturer="OSRAM Opto Semiconductors Inc.", Manufacturer Part Number="LY R976-PS-36", Millicandela Rating=162.5mcd, Package / Case="0805 (2012 Metric)", Supplier Device Package=0805, Supplier Part Number 1=475-2560-1-ND, Voltage - Forward (Vf) (Typ)=2V
D3: "BAT60AE6327HTSA1", Average Rectified Current=3A, Forward Voltage=370mV, Manufacturer=Infineon, Max Operating Temperature=85°C, Max Repetitive Reverse Voltage (Vrrm)=10V, Min Operating Temperature=-55°C, Peak Non-Repetitive Surge Current=5A, Supplier Part Number 1=726-BAT60AE6327
H1: Case/Package=0805, Case Code (Metric)=2012, Current Rating=700mA, DC Resistance (DCR)=260mR, Inductance=4.7uh, Manufacturer=TDK, Manufacturer Part Number=MLP2012S4R7MT0S1, Max Operating Temperature=125°C, Min Operating Temperature=-40°C, Package Quantity=4000, Supplier Part Number 1=810-MLP2012S4R7MT0S1, Test Frequency=2MHz, Tolerance=20%
J1: "USB_Connector_5P_MICRO_USB_FCI", Current Rating="1.8A per Contact", Insulation Color=Black, Manufacturer="Amphenol FCI", Manufacturer Part Number=10118194-0001LF, Material Flammability Rating="UL94 V-0", Operating Temperature="-30°C ~ 80°C", Supplier Part Number 1=609-4618-1-ND, Voltage - Rated=100VAC
J2 J3 J4 J5 J6 J7 J8 J9 J10 J11 J12 J13 J14 J15 J16 J17 J18 J19 J20 J21 J22 J23 J24 J25 J26: library part CON-1_Pin_Thread, "Header, 1 pin, Conductive Thread"
J28: library part CON-6Pin-100Mil, "Header, 6 pin, .1 pitch", Current Rating=-, Insulation Color=Black, Manufacturer="Amphenol FCI", Manufacturer Part Number=68000-406HLF, Material Flammability Rating="UL94 V-0", Supplier Part Number 1=609-3263-ND
J30: "CONN HEADER .050\" 10PS DL SMD AU", Color=-, Manufacturer="Sullins Connector Solutions", Supplier Part Number 1=S9013E-05-ND
Q1 Q2: library part FMMT591CT-ND, "Transistor PNP", Current - Collector (Ic) (Max)=1A, Current - Collector Cutoff (Max)=100nA, DC Current Gain (hFE) (Min) @ Ic, Vce="100 @ 500mA, 5V", Frequency - Transition=150MHz, Manufacturer="Diodes Incorporated", Manufacturer Part Number=FMMT591TA, Operating Temperature="-55°C ~ 150°C (TJ)", Package / Case="TO-236-3, SC-59, SOT-23-3", Power - Max=500mW, Supplier Device Package=SOT-23-3, Voltage - Collector Emitter Breakdown (Max)=60V
Q3: Case/Package=SOT-23, Continuous Drain Current (ID)=4A, Drain to Source Breakdown Voltage=-12V, Drain to Source Resistance=31mR, Drain to Source Voltage (Vdss)=12V, Gate to Source Voltage (Vgs)=8V, Input Capacitance=1.357nF, Manufacturer=Diodes, Manufacturer Part Number=DMP1045U-7, Max Operating Temperature=150°C, Max Power Dissipation=800mW, Min Operating Temperature=-55°C, Package Quantity=3000, Power Dissipation=1.3W, Supplier Part Number 1=621-DMP1045U-7
R1 R2: library part R-0805(2012), "___ OHM ___ mW 0805(2012) SMD", Manufacturer=Yageo, Manufacturer Part Number=RC0805JR-0727RL, Operating Temperature="-55°C ~ 155°C", Package / Case="0805 (2012 Metric)", Power (Watts)="0.125W, 1/8W", Supplier Device Package=0805, Supplier Part Number 1=311-27ARCT-ND, Temperature Coefficient=±100ppm/°C, Tolerance=±5%
R3 R4: library part R-0805(2012), "___ OHM ___ mW 0805(2012) SMD", Manufacturer=Yageo, Manufacturer Part Number=RC0805JR-0730RL, Operating Temperature="-55°C ~ 155°C", Package / Case="0805 (2012 Metric)", Power (Watts)="0.125W, 1/8W", Supplier Device Package=0805, Supplier Part Number 1=311-30ARCT-ND, Temperature Coefficient=±100ppm/°C, Tolerance=±5%
R5 R6: library part R-0805(2012), "___ OHM ___ mW 0805(2012) SMD", Manufacturer=Yageo, Manufacturer Part Number=RC0805JR-071KL, Operating Temperature="-55°C ~ 155°C", Package / Case="0805 (2012 Metric)", Power (Watts)="0.125W, 1/8W", Supplier Device Package=0805, Supplier Part Number 1=311-1.0KARCT-ND, Temperature Coefficient=±100ppm/°C, Tolerance=±5%
R7 R11: library part R-0805(2012), "___ OHM ___ mW 0805(2012) SMD", Case/Package=0805, Case Code (Metric)=2012, Manufacturer=Yageo, Manufacturer Part Number=RC0805FR-0710KL, Max Operating Temperature=155°C, Max Power Dissipation=125mW, Min Operating Temperature=-55°C, Package Quantity=1, Supplier Part Number 1=603-RC0805FR-0710KL, Temperature Coefficient=100ppm/°C, Tolerance=1%, Voltage Rating=150V
R8: library part R-0805(2012), "___ OHM ___ mW 0805(2012) SMD"
R9: library part R-0805(2012), "___ OHM ___ mW 0805(2012) SMD", Case/Package=0805, Case Code (Metric)=2012, Manufacturer="Panasonic ECG", Manufacturer Part Number=ERJ-6ENF9763V, Max Operating Temperature=155°C, Max Power Dissipation=125mW, Min Operating Temperature=-55°C, Package Quantity=1, Supplier Part Number 1=667-ERJ-6ENF9763V, Temperature Coefficient=100ppm/°C, Tolerance=1%, Voltage Rating=150V
R10: library part R-0805(2012), "___ OHM ___ mW 0805(2012) SMD", Case/Package=0805, Case Code (Metric)=2012, Manufacturer=Vishay, Manufacturer Part Number=CRCW0805562KFKEA, Max Operating Temperature=155°C, Max Power Dissipation=125mW, Min Operating Temperature=-55°C, Package Quantity=10, Supplier Part Number 1=71-CRCW0805-562K-E3, Temperature Coefficient=100ppm/°C, Tolerance=1%, Voltage Rating=150V
T1: library part CRYSTAL_8MHz, "Oscillator Crystal 8MHz 10ppm", ESR (Equivalent Series Resistance)="72 Ohm", Frequency Stability=±20ppm, Load Capacitance=18pF, Manufacturer="Abracon LLC", Manufacturer Part Number=ABMM2-8.000MHZ-E2-T, Operating Mode=Fundamental, Operating Temperature="-20°C ~ 70°C", Package / Case="4-SMD, No Lead", Ratings=-, Supplier Part Number 1=535-9628-1-ND
U1: "USB to Basic UART Interface Chip, UHCI/OHCI/EHCI Compatible, USB 2.0 Compatible, -40 to +85 degC, 16-Pin QFN, Pb-Free, Tape and Reel", Current - Supply=8mA, Manufacturer="FTDI, Future Technology Devices International Ltd", Operating Temperature="-40°C ~ 85°C", Package / Case="16-WQFN Exposed Pad", Supplier Device Package="16-QFN (4x4)", Supplier Part Number 1=768-1130-1-ND, Voltage - Supply="3.3 V ~ 5 V"
U2 U3: Manufacturer="Analog Devices Inc.", Manufacturer Part Number=AD7147PACPZ-500R7, Operating Temperature="-40°C ~ 85°C", Package / Case="24-WFQFN Exposed Pad, CSP", Supplier Device Package="24-LFCSP-WQ (4x4)", Supplier Part Number 1=AD7147PACPZ-500R7CT-ND, Voltage - Supply="2.6 V ~ 3.6 V", Voltage Supply Source="Single Supply"
U4: Manufacturer="Microchip Technology", Manufacturer Part Number=PIC18F25K80T-I/MM, Operating Temperature="-40°C ~ 85°C (TA)", Package / Case="28-VQFN Exposed Pad", Supplier Device Package="28-QFN-S (6x6)", Supplier Part Number 1=PIC18F25K80T-I/MMCT-ND, Voltage - Supply (Vcc/Vdd)="1.8 V ~ 5.5 V"
U5: Case/Package=SOT-89, Dropout Voltage=1.7V, Manufacturer=STMicroelectronics, Max Input Voltage=30V, Max Operating Temperature=125°C, Max Output Current=100mA, Min Input Voltage=5.3V, Min Operating Temperature=0°C, Min Output Voltage=3.3V, Output Voltage Accuracy=4%, Package Quantity=2500, Power Supply Rejection Ratio (PSRR)=49dB, Quiescent Current=6mA, Supplier Part Number 1=511-L78L33ACU
U6: "CLASS 2 BLTOOTH 4.0 MODULE", Current - Receiving=25mA, Current - Transmitting=36mA, Frequency=2.4GHz, Manufacturer="Silicon Labs", Operating Temperature="-40°C ~ 85°C", Package / Case=Module, Power - Output=3dBm, Supplier Part Number 1=1446-1017-1-ND, Voltage - Supply="2 V ~ 3.6 V"
U7: "3D accelerometer and 3D gyroscope", Manufacturer=STMicroelectronics, Manufacturer Part Number=LSM6DS3HTR, Operating Temperature="-40°C ~ 85°C (TA)", Supplier Part Number 1=497-16367-1-ND
U8: library part CMP-0139-00285-1, "Start-up Synchronous Boost Regulator with True Output Disconnect or Input / Output Bypass Option, 350 mA, Input Voltage 0.65 to 5.5 V, Output Voltage 2.0 to 5.5 V, -40 to 85 degC, 6-pin SOT-23 (CHY6), Tape and Reel", Case/Package=SOT-23, Frequency=500KHz, Manufacturer=Microchip, Max Input Voltage=5.5V, Max Operating Temperature=85°C, Max Output Current=350mA, Min Input Voltage=650mV, Min Operating Temperature=-40°C, Min Output Voltage=2V, Package Quantity=3000, Supplier Part Number 1=579-MCP1640BT-I/CHY

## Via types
v1: diameter 30, hole 15, Top Layer to Bottom Layer, 58 vias

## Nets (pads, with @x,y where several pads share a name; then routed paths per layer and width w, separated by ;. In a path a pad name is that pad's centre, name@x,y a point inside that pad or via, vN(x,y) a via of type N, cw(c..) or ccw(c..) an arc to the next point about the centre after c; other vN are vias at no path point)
3.3V: C1.1 C4.1 C6.1 C11.2 C12.2 C13.1 C14.1 D1.A D2.A J28.2 J30.2 Q3.3 R7.2 U1.1 U1.8 U1.10 U2.11 U2.12 U3.11 U3.12 U4.3 U4.17 U5.1 U6.2 U6.3 U6.20 U7.2 U7.3 U7.5 U7.8 | length 9388.5
  Top Layer w10: v1(95,995) 190,995 ; U5.1@187.4,1033.23 187.4,997.6 190,995 ; J30.2 451.18,396.18 470,415 J28.2 470,530 485,545 565,545 584.45,564.45 R7.2 ; U1.8 463.15,1321.85 485,1300 522.2,1300 ; U1.10 522.2,1300 ; U1.1 606.85,1551.85 610,1555 v1(660,1555) ; D1.A 1020,615 1045,640 1200,640 1215,625 v1(1215,590) ; D2.A 1320,1495 1361,1454 1361,1214.23 1350,1203.23 1350,1140 1380,1110 v1(1415,1110) ; 190,995 295.55,995 C6.1 398.39,993.39 419.72,1014.72 Q3.3 452.6,1047.6 470,1065 470,1130 522.2,1182.2 522.2,1300
  Ground w10: v1(390,1430) 390,1485 460,1555 v1(660,1555) 660,1580 700,1620 965,1620 1040,1545 1040,835 v1(1025,820) ; J28.2 470,735 555,820 v1(1025,820) ; v1(1415,1110) 1360,1110 1070,820 v1(1025,820) ; v1(1610,835) 1480,835 1375,730 1375,655 1310,590 v1(1215,590) 1100,590 1025,665 v1(1025,820)
  Bottom Layer w10: U6.3 U6.2 95,1192.52 v1(95,995) 480,995 647.64,827.36 U6.20 818.78,827.36 ; v1(390,1430) 400,1430 405,1425 ; U7.2 438.58,1420 410,1420 405,1425 ; U7.8 531.26,1528.74 C11.2 465.63,1530 C12.2 U7.5 465.32,1440.32 464.84,1439.84 U7.3 409.84,1439.84 405,1435 405,1425 ; U4.3 1064.41,949.41 1050,935 1050,845 v1(1025,820) 1025,760 1011.44,746.44 837.7,746.44 819,765.14 819,795.77 825,801.77 825,821.15 818.78,827.36 ; U3.11 U3.12 1053.23,1398.23 1030,1375 955,1375 945,1365 C1.1 894.45,1339.45 818.78,1263.78 818.78,827.36 ; U2.11 1154.53,584.53 1160,590 1174.21,590 ; U2.12 1174.21,590 ; C4.1@1270,580 1260,590 v1(1215,590) 1174.21,590 ; U4.17 1360.59,1000.59 1415,1055 v1(1415,1110) C14.1 ; C13.1 v1(1610,835)
3.3V_BAT: C16.1 Q3.2 R9.1 U8.5 | length 409.6
  Top Layer w10: U8.5 545,940 536.1,948.9 R9.1 510,1026.1 510,1084.72 Q3.2 570,1085 624.45,1139.45 C16.1
A_INT1: U4.20 U7.4 | length 1893.9
  Signal Layer 1 w10: v1(700,1280) 700,820 790,730 1340,730 1355,745 v1(1355,770)
  Bottom Layer w10: U7.4 374.53,1459.53 355,1440 355,1405 470,1290 690,1290 v1(700,1280) ; U4.20 1351.18,923.82 1365,910 1365,850 1355,840 v1(1355,770)
A_INT2: U4.21 U7.9 | length 1548.6
  Signal Layer 1 w10: v1(665,1440) 625,1440 605,1420 605,1360 645,1320 845,1320 910,1255 910,880 1005,785 v1(1315,785)
  Bottom Layer w10: U7.9 664.84,1439.84 v1(665,1440) ; v1(1315,785) 1315,850 1328.11,863.11 U4.21
B_V: B1.2 B2.2 C17.1 H1.2 U8.3 U8.6 | length 2184.5
  Top Layer w10: U8.6 462.24,897.24 449.45,884.45 C17.1 H1.2 259.45,884.45 245,870 245,790 265,770 575,770 582.4,777.4 U8.3 667.24,802.76 721,749 840.39,749 851.98,760.59 875,760.59 B1.2@1225,760.59 ; v1(875,1209.41) B1.2@1225,1209.41
  Signal Layer 1 w10: v1(845,785) 845,1080 875,1110 v1(875,1209.41)
CLK_IN: C7.1 T1.1 U4.6 | length 416.7
  Bottom Layer w10: C7.1 885.55,865.59 T1.1 872.76,942.76 900,970 985,970 1041.18,1026.18 U4.6
CLK_OUT: C8.1 T1.3 U4.7 | length 223.4
  Bottom Layer w10: C8.1 954.45,1064.41 T1.3 967.4,1051.77 U4.7
CS1: U2.16 U4.9 | length 1444.6
  Signal Layer 1 w10: v1(1230,1305) 1230,1100 1455,875 1455,800.3 1375,720.3 1375,445 1350,420 v1(1310,420)
  Bottom Layer w10: U4.9 1158.82,1158.82 1230,1230 v1(1230,1305) ; U2.16 1289.84,465.16 1310,445 v1(1310,420)
CS2: U3.16 U4.8 | length 885
  Top Layer w10: v1(880.5,1510.5) 880.5,1409.5 955,1335 1175,1335 1200,1310 v1(1200,1275)
  Bottom Layer w10: v1(880.5,1510.5) 881,1511 961.63,1511 987.63,1485 1000,1485 1000.16,1484.84 U3.16 ; U4.8 1133.23,1155.86 1200,1222.63 v1(1200,1275)
CS3: U4.10 U7.12 | length 1064.2
  Signal Layer 1 w10: v1(665,1385) 900,1385 935,1350 v1(1230,1350)
  Bottom Layer w10: U7.12 504.68,1380.32 519,1366 570,1366 589,1385 v1(665,1385) ; U4.10 1184.41,1154.41 1256,1226 1256,1315.77 1230,1341.77 v1(1230,1350)
CS_BLE: U4.22 U6.24 | length 1122.4
  Bottom Layer w10: U6.24 534.96,650.04 566,619 661.63,619 691,648.37 691,677.77 738.23,725 1100,725 1179,646 1256,646 1286.77,676.77 U4.22
GND: B1.1 B2.1 C1.2 C2.2 C3.2 C4.2 C5.2 C6.2 C7.2 C8.2 C9.1 C10.1 C11.1 C12.1 C13.2 C14.2 C15.2 C16.2 J1.5 J26.1 J28.3 J30.1 Q1.2 Q2.2 R10.2 R11.1 T1.2 U1.3 U1.13 U1.17 U2.10 U2.25 U3.10 U3.25 U4.5 U4.16 U4.29 U5.2 U6.1 U6.10 U6.21 U6.30 U7.6 U7.7 U8.2 | length 2285.1
  Top Layer w10: U5.2@185.43,1092.28 297.17,1092.28 ; C6.2 297.17,1092.28 ; C2.2 297.17,1092.28 ; J28.3 570,490 645,565 645,690 630,705 C15.2 ; B2.1 B1.1
  Bottom Layer w10: U7.6 495,1466.42 ; U7.7 495,1466.42 ; v1(505,1480) 508.58,1480 495,1466.42 ; U6.21 723.54,774.61 723.93,775 v1(790,775) ; T1.2@872.76,1051.61 885.55,1064.41 C8.2 ; C1.2 995,1270.55 995,1345 1000,1350 1100,1350 1115.16,1365.16 U3.10 1115.16,1465.16 U3.25 ; C7.2 954.45,865.59 T1.2@967.24,878.39 ; v1(1000,945) 1055.59,1000.59 U4.5 1184.41,1000.59 U4.29 1261.18,1026.18 U4.16 ; U2.25 1125,505 1134.84,514.84 U2.10 1134.84,614.84 1150,630 1330,630 1339.45,620.55 C4.2
  other v1: 865,690 45,985 1095,1245 45,1475 735,1510 165,1620
ICSPCLK: J28.5 U4.24 | length 818.4
  Signal Layer 1 w10: J28.5 770,570 832.5,632.5 1222.5,632.5 1240,650 v1(1240,700)
  Bottom Layer w10: U4.24 1235.59,814.41 1260,790 1260,720 v1(1240,700)
ICSPDAT: J28.4 U4.25 | length 858.3
  Signal Layer 1 w10: J28.4 670,575 695,600 777.37,600 825.87,648.5 1183.5,648.5 v1(1210,675)
  Bottom Layer w10: v1(1210,675) U4.25
INT_1: U2.17 U4.18 | length 888.3
  Top Layer w10: v1(1275,420) 1275,395 1295,375 1355,375 1376,396 1376,726 1415,765 v1(1415,840)
  Bottom Layer w10: U2.17 1264.53,445.47 1275,435 v1(1275,420) ; U4.18 1365,975 1401,939 1401,854 v1(1415,840)
INT_2: U3.17 U4.19 | length 1693
  Top Layer w10: v1(855.22,1543.19) 833.19,1543.19 780,1490 780,1155 855,1080 1340,1080 1385,1035 v1(1385,815)
  Bottom Layer w10: v1(855.22,1543.19) 859.41,1539 956.25,1539 990.73,1504.53 U3.17 ; U4.19 1360.59,949.41 1385,925 v1(1385,815)
MCLR: J28.1 R8.1 U4.26 | length 1258.1
  Top Layer w10: J28.1 R8.1
  Signal Layer 1 w10: J28.1 370,570 420,620 774.75,620 819.25,664.5 1154.5,664.5 1180,690 v1(1180,700)
  Bottom Layer w10: v1(1180,700) 1184.41,695.59 U4.26 U4.26@1185,856.3
MISO: U2.13 U3.13 U4.12 U6.26 U7.1 | length 4849.5
  Top Layer w10: v1(972.5,1405) 1275,1405 1305,1375 v1(1305,1270)
  Signal Layer 1 w10: v1(972.5,1405) 755,1405 692,1468 613,1468 580,1435 580,1345 660,1265 660,820 775,705 v1(775,675) 775,660 751,636 396,636 305,545 305,430 330,405 880,405 1020,545 v1(1240,545)
  Bottom Layer w10: U6.26 436.54,633.46 483,587 722,587 775,640 v1(775,675) ; U7.1 438.74,1366.26 495,1310 825,1310 920,1405 v1(972.5,1405) 990,1405 1010.79,1425.79 U3.13 ; U2.13 1229.21,524.21 1240,535 v1(1240,545) ; U4.12 1235.59,1145.59 1305,1215 v1(1305,1270)
MOSI: U2.14 U3.14 U4.13 U6.25 U7.14 | length 4864.3
  Top Layer w10: v1(945,1445) 1275,1445 1335,1385 v1(1335,1225)
  Signal Layer 1 w10: v1(945,1445) 925,1425 757.63,1425 698.63,1484 606.37,1484 564,1441.63 564,1338.37 644,1258.37 644,806 725,725 v1(725,675) 725,660 717,652 389.37,652 289,551.63 289,423.37 332.37,380 890,380 1000,490 1260,490 1275,505 v1(1275,525)
  Bottom Layer w10: U7.14 465.32,1369.68 505,1330 815,1330 930,1445 v1(945,1445) 970,1445 ; U6.25 485.75,629.25 512,603 698,603 725,630 v1(725,675) ; U3.14 1047.76,1445 971,1445 ; U2.14 1202.3,504 1269,504 1275,510 v1(1275,525) ; U4.13 1261.18,1131.18 1335,1205 v1(1335,1225) ; 970,1445 971,1445 ; 970,1445 971,1446 971,1445
NetAC1_1: AC1.1 U2.8 | length 3129.4
  Bottom Layer w10: U2.8 1095.47,589.53 1075,610 970,610 915,555 190,555 140,505 140,385 19,264 19,96 65,50 AC1.1
NetAC2_1: AC2.1 U3.8 | length 1640.7
  Top Layer w10: v1(1075,1175) 1075,1155 1130,1100 1360,1100 1390,1070 1505,1070 1630,1195 AC2.1
  Bottom Layer w10: v1(1075,1175) 1105,1175 1154.53,1224.53 U3.8
NetC2_1: C2.1 D3.1 U5.3 | length 253.4
  Top Layer w10: D3.1 126.1,1208.9 138.82,1196.18 190,1196.18 ; U5.3@187.4,1151.34 190,1153.94 190,1196.18 ; C2.1 190,1196.18
NetC3_1: C3.1 U2.9 | length 156.6
  Bottom Layer w10: C3.1 1095,670 1115.16,649.84 U2.9
NetC5_1: C5.1 U3.9 | length 160.2
  Bottom Layer w10: C5.1 1094.45,1309.45 1134.84,1349.84 U3.9 U3.9@1135,1398.07
NetC9_2: C9.2 R2.2 U1.6 | length 274.2
  Top Layer w10: R2.2 334.45,1589.45 334.45,1614.45 340,1620 C9.2 415.55,1509.45 432.2,1492.8 U1.6
NetC10_2: C10.2 R1.2 U1.7 | length 263.5
  Top Layer w10: C10.2@335,1319.45 R1.2 406.1,1381.1 420,1395 420,1460 427.2,1467.2 U1.7
NetC15_1: C15.1 R7.1 R8.2 | length 171.7
  Top Layer w10: R8.2 R7.1 C15.1
NetC17_2: C17.2 H1.1 U8.1 | length 212.9
  Top Layer w10: H1.1 C17.2 459.45,815.55 472.24,802.76 U8.1
NetD1_K: D1.K R3.2 | length 105.2
  Top Layer w10: R3.2 1094.45,579.45 D1.K
NetD2_K: D2.K R4.2 | length 90.2
  Top Layer w10: R4.2 1289.45,1569.45 D2.K
NetJ1_2: J1.2 R2.1 | length 155.1
  Top Layer w10: J1.2 310.59,1495.59 R2.1
NetJ1_3: J1.3 R1.1 | length 153.3
  Top Layer w10: J1.3 315,1470 R1.1
NetQ1_1: Q1.1 R5.1 | length 80
  Top Layer w10: Q1.1 R5.1
NetQ1_3: Q1.3 R3.1 | length 85.1
  Top Layer w10: Q1.3 1025.2,474.65 R3.1
NetQ2_1: Q2.1 R6.2 | length 72.9
  Top Layer w10: R6.2 985.83,1499.72 Q2.1
NetQ2_3: Q2.3 R4.1 | length 67.9
  Top Layer w10: Q2.3 1133.23,1500.55 R4.1
NetR5_2: R5.2 U2.18 | length 194.3
  Top Layer w10: R5.2 1231.1,321.1 1240,330 v1(1240,420)
  Bottom Layer w10: U2.18 1207.56,420 v1(1240,420)
NetR6_1: R6.1 U3.18 | length 245.7
  Top Layer w10: v1(900,1565) R6.1@980.55,1565
  Bottom Layer w10: v1(900,1565) 960,1565 1000.79,1524.21 U3.18
NetR9_2: R9.2 R10.1 U8.4 | length 233
  Top Layer w10: U8.4 582.4,927.4 605,950 R9.2 640,1000 665,975 R10.1
P2_1: J30.4 U6.5 | length 1914.8
  Top Layer w10: v1(190,325) J30.4
  Signal Layer 1 w10: v1(75,1515) 215,1515 280,1450 280,700 250,670 250,625 186.28,561.28 186.28,328.72 v1(190,325)
  Bottom Layer w10: v1(75,1515) 175,1515 239.68,1450.32 U6.5
P2_2: J30.3 U6.4 | length 1343.7
  Top Layer w10: J30.3 v1(190,610)
  Signal Layer 1 w10: v1(75,1430) 215,1430 244,1401 244,699 190,645 v1(190,610)
  Bottom Layer w10: v1(75,1430) 110,1430 140,1400 140,1330 190.47,1279.53 U6.4
RESET: J30.7 U6.29 | length 358
  Top Layer w10: J30.7 v1(90,645)
  Bottom Layer w10: v1(90,645) v1(290,645) 290,719.96 U6.29
RX: U1.15 U4.15 | length 1412.9
  Top Layer w10: U1.15 662.8,1492.8 809,1639 1301,1639 1380,1560 v1(1380,1170)
  Bottom Layer w10: U4.15 1356.77,1051.77 1380,1075 v1(1380,1170)
S1: J13.1 U2.19 | length 596
  Bottom Layer w10: U2.19 1191.44,381 1316,381 1340,405 1340,495 1380,535 1380,660 1420,700 J13.1
S2: J12.1 U2.20 | length 496.6
  Bottom Layer w10: U2.20 1154.53,375.47 1165,365 1325,365 1370,410 1370,500 1395,525 J12.1
S3: J11.1 U2.21 | length 407.4
  Bottom Layer w10: U2.21 1134.84,370.16 1156,349 1504,349 J11.1
S4: J10.1 U2.22 | length 516.5
  Bottom Layer w10: U2.22 1115.16,359.84 1145,330 1370,330 1505,195 J10.1
S5: J6.1 U2.23 | length 420
  Bottom Layer w10: U2.23 1095.47,344.53 1130,310 1300,310 1330,280 J6.1
S6: J9.1 U2.24 | length 270.7
  Bottom Layer w10: U2.24 1075.79,329.21 1115,290 1140,290 1155,275 J9.1
S7: J8.1 U2.1 | length 279
  Bottom Layer w10: J8.1 980,300 1048.23,368.23 U2.1
S8: J7.1 U2.2 | length 434.6
  Bottom Layer w10: J7.1 805,285 820,300 895.51,300 999,403.49 999,429 1015.47,445.47 U2.2
S9: J5.1 U2.3 | length 610.4
  Bottom Layer w10: J5.1 630,270 680,320 892.88,320 983,410.12 983,438 1010.16,465.16 U2.3
S10: J4.1 U2.4 | length 806.7
  Bottom Layer w10: J4.1 455,285 510,340 890.25,340 967,416.75 967,452 999.84,484.84 U2.4
S11: J3.1 U2.5 | length 1000
  Bottom Layer w10: J3.1 280,295 341,356 883.63,356 951,423.37 951,466 989.53,504.53 U2.5
S12: J2.1 U2.6 | length 1164.4
  Bottom Layer w10: J2.1 105,260 130,285 247.37,285 334.37,372 877,372 935,430 935,475 984.21,524.21 U2.6
S13: J14.1 U3.19 | length 1086.3
  Bottom Layer w10: J14.1 125,1775 301,1599 494,1599 506,1611 945.86,1611 956.86,1600 1050,1600 1075.79,1574.21 U3.19
S14: J15.1 U3.20 | length 1010.3
  Bottom Layer w10: J15.1 280,1650 315,1615 487.37,1615 499.37,1627 952.49,1627 963.49,1616 1064,1616 1095.47,1584.53 U3.20
S15: J16.1 U3.21 | length 836.4
  Bottom Layer w10: J16.1 455,1670 482,1643 959.12,1643 970.12,1632 1073,1632 1115.16,1589.84 U3.21
S16: J17.1 U3.22 | length 678.4
  Bottom Layer w10: J17.1 630,1685 655,1660 817.37,1660 818.37,1659 965.75,1659 976.75,1648 1087,1648 1134.84,1600.16 U3.22
S17: J18.1 U3.23 | length 523.2
  Bottom Layer w10: J18.1 805,1695 825,1675 972.37,1675 983.37,1664 1101,1664 1154.53,1610.47 U3.23
S18: J19.1 U3.24 | length 374
  Bottom Layer w10: J19.1 980,1690 990,1680 1110,1680 1174.21,1615.79 U3.24
S19: J20.1 U3.1 | length 412.5
  Bottom Layer w10: J20.1 1155,1680 1175,1660 1260,1660 1280,1640 1280,1555 1249.21,1524.21 U3.1
S20: J21.1 U3.2 | length 375
  Bottom Layer w10: U3.2 1289.53,1504.53 1300,1515 1300,1620 1330,1650 J21.1
S21: J22.1 U3.3 | length 470.3
  Bottom Layer w10: U3.3 1294.84,1484.84 1330,1520 1330,1600 J22.1
S22: J23.1 U3.4 | length 386.3
  Bottom Layer w10: U3.4 1310.16,1465.16 1355,1510 1355,1565 1390,1600 J23.1
S23: J24.1 U3.5 | length 306.7
  Bottom Layer w10: U3.5 1254.53,1445.47 1275,1425 J24.1
S24: J25.1 U3.6 | length 394.6
  Bottom Layer w10: U3.6 1251.59,1425.79 1268.37,1409 1381.24,1409 1440.15,1350.09 1440.15,1309.85 J25.1
SCLK: U2.15 U3.15 U4.11 U6.23 U7.13 | length 4772.1
  Top Layer w10: v1(915,1485) 915,1400 936,1379 983.27,1379 989.27,1385 1250,1385 v1(1277,1358) v1@1274,1355
  Signal Layer 1 w10: v1(915,1485) 885,1455 750.25,1455 705.25,1500 599.75,1500 548,1448.25 548,1331.75 628,1251.75 628,799.37 675,752.37 v1(675,700) 675,685 658,668 382.75,668 273,558.25 273,416.75 325.75,364 896.63,364 997.63,465 1270,465 1310,505 v1(1310,525)
  Bottom Layer w10: U7.13 485,1375 510,1350 810,1350 915,1455 v1(915,1485) 965,1485 984.84,1465.16 U3.15 ; U6.23 584.17,650.83 600,635 655,635 675,655 v1(675,700) ; U2.15 1299.84,484.84 1310,495 v1(1310,525) ; U4.11 1210,1150 1275,1215 1275,1356 v1(1277,1358)
TX: U1.2 U4.14 | length 1516
  Top Layer w10: U1.2 547.8,1597.8 620,1670 1330,1670 1406.22,1593.78 v1(1406.22,1331.39)
  Bottom Layer w10: U4.14 1286.77,1125.56 1406.22,1245 v1(1406.22,1331.39)
V_USB: D3.2 J1.1 Q3.1 R11.2 | length 745.6
  Top Layer w10: J1.1 141.18,1521.18 135,1515 135,1350 180,1305 260,1305 277.8,1287.2 277.8,1240 ; D3.2 277.8,1240 ; Q3.1 419.72,1209.17 R11.2 385,1210 355,1240 277.8,1240
pads on no net: D1.0 D2.0 J1.4 J1.15 J1.16 J1.18 J28.6 J30.5 J30.6 J30.8 J30.9 J30.10 J30.21 J30.22 Q1.0 Q2.0 Q3.0 U1.4 U1.5 U1.9 U1.11 U1.12 U1.14 U1.16 U2.7 U3.7 U4.1 U4.2 U4.4 U4.23 U4.27 U4.28 U5.0 U6.6 U6.7 U6.8 U6.9 U6.11 U6.12 U6.13 U6.14 U6.15 U6.16 U6.17 U6.18 U6.19 U6.22 U6.27 U6.28 U7.10 U7.11

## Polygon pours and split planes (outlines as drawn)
GND on Bottom Layer "GND_Ground_Bottom" (solid, remove dead copper, pour order 14): 5,5 5,1945 1670,1945 1670,5
NetAC2_1 on Bottom Layer "AC_Shield_2" (solid, remove dead copper, pour order 12): 5,1945 5,1640 1185,1640 1185,1515 1410,1290 1410,1185 1440,1155 1670,1155 1670,1945
NetAC1_1 on Bottom Layer "AC_Shield_1" (solid, remove dead copper, pour order 8): 5,5 5,565 825,565 825,570 1405,570 1405,765 1670,765 1670,5
GND on Top Layer "Top_Layer_GND" (solid, remove dead copper, pour order 0): 5,5 5,1945 1670,1945 1670,5
GND on Ground "Ground_GND" (solid, remove dead copper, pour order 6): 5,5 5,1945 1670,1945 1670,5
GND on Signal Layer 1 "Signal_Layer_1_GND" (solid, remove dead copper, pour order 2): 5,5 5,1945 1670,1945 1670,5

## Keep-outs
Top Layer:
  lines w10: 25,675 25,935 225,935 225,820 200,795 200,685 190,675 25,675
Signal Layer 1:
  lines w10: 25,675 190,675 200,685 200,795 225,820 225,935 25,935 25,675
Ground:
  lines w10: 25,675 25,935 225,935 225,820 200,795 200,685 190,675 25,675
Bottom Layer:
  lines w10: 25,675 25,935 225,935 225,820 200,795 200,685 190,675 25,675
Keep-Out Layer:
  the board outline again, w10

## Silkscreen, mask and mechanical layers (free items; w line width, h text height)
Mechanical 3:
  the board outline again, w10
